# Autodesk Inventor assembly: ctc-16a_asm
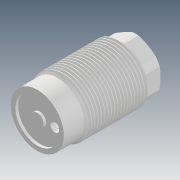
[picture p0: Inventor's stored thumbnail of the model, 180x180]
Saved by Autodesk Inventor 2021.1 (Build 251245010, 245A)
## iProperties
Created: 2018-08
Part Number: ctc-16a_asm
Description: STEP AP203
Document SubType Name: Assembly
Designer: user
Title: ctc-16a_asm.STEP
Revision Number: ÈÎºÎ
Sending System: SolidWorks 2015
Preprocessor: SwSTEP 2.0
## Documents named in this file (6)
- D:\Vault_2016\Projekty\Clamptek\Hydraulic\CTC\Inventor\ctc-16a\ctc-16a_asm.iam
- D:\Vault_2016\Projekty\Clamptek\Hydraulic\CTC\Inventor\ctc-16a\CTC-16ABT.ipt
- D:\Vault_2016\Projekty\Clamptek\Hydraulic\CTC\Inventor\ctc-16a\CTC-16AHSG.ipt
- D:\Vault_2016\Projekty\Clamptek\Hydraulic\CTC\Inventor\ctc-16a\CTC-16AHG.ipt
- D:\Vault_2016\Projekty\Clamptek\Hydraulic\CTC\Inventor\ctc-16a\CTC-16AMD.ipt
- D:\Vault_2016\Projekty\Clamptek\Hydraulic\CTC\Inventor\ctc-16a\CTC-16DP.ipt
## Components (5 placed, 5 different names)
1. CTC-16ABT_1
2. CTC-16AHSG_2
3. CTC-16AHG_3
4. CTC-16AMD_4
5. CTC-16DP_5
